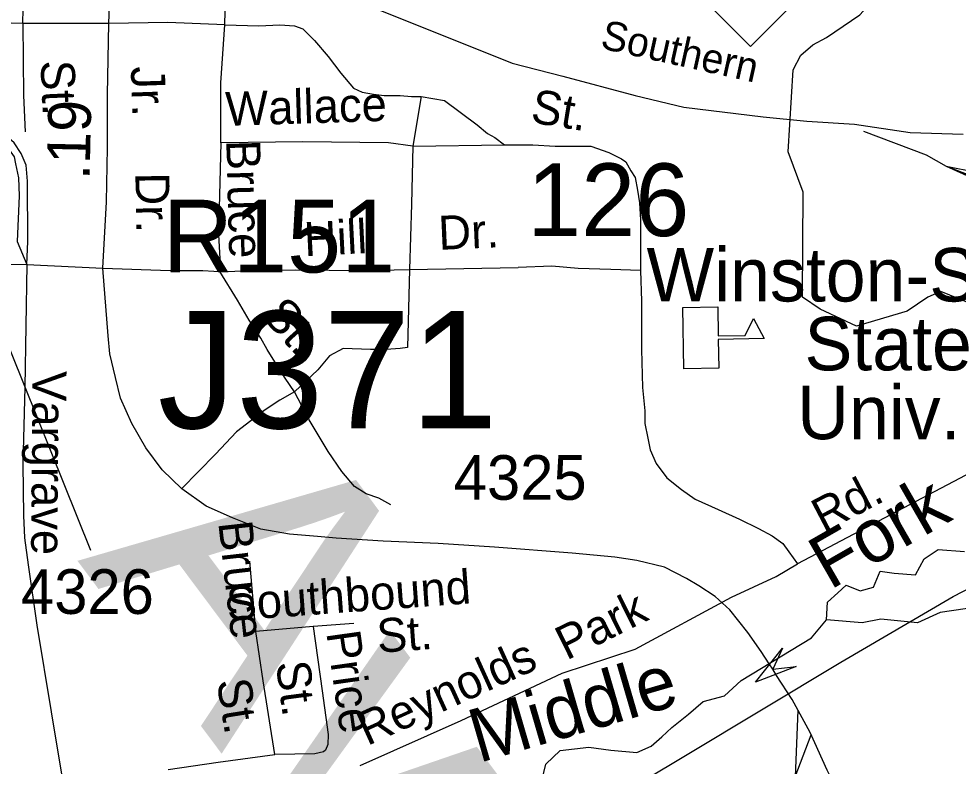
# Model space of a CAD drawing. Extents: x 1553981 to 1780076, y 812965 to 996873.
# Drawn here: x 1634089 to 1634417.6, y 847717.4 to 847978.9 of the extents above; entities that cross this region are included whole.
import ezdxf

# ---------------------------------------------------------------- set-up
doc = ezdxf.new("R2010")
doc.units = 0
for name, color, linetype in [('Exist Aviation Field Marked Auxiliary Label', 7, 'Continuous'), ('Exist Hydrographic Creek Single Shore', 7, 'Continuous'), ('Exist Hydrographic Creek Single Shore Label', 7, 'Continuous'), ('Exist Railroad Mainline', 7, 'Continuous'), ('Exist Railroad Mainline Label', 7, 'Continuous'), ('Exist Railroad Siding', 7, 'Continuous'), ('Exist Railroad Station CELL', 7, 'Continuous'), ('Exist Road Non-System Structure Non-Sys Other Number Label', 7, 'Continuous'), ('Exist Road Non-System Type 51 Label', 7, 'Continuous'), ('Exist Road Primary US Ramp 1 Lane  Attributed', 7, 'Continuous'), ('Exist Road Primary US Structure RailRoad Number Label', 7, 'Continuous'), ('Exist Road Secondary Mileage Hundredths English Label', 7, 'Continuous'), ('Exist Road Secondary Structure Standard Bridge Attributed CELL', 7, 'Continuous'), ('Exist Road Secondary Structure Standard Bridge Number Label', 7, 'Continuous'), ('Exist Road Secondary Type 51 Number Label', 7, 'Continuous'), ('Exist Road Secondary Type 51 Undivided 4 Lane Attributed', 7, 'Continuous'), ('Exist Utilities Electrical Transmission Line', 7, 'Continuous'), ('Map Preparation Border Antique Large Shape', 7, 'Continuous'), ('Map Preparation Border County Name Lower Right Label', 7, 'Continuous'), ('Map Preparation Border Division and District Label', 7, 'Continuous')]:
    doc.layers.add(name, color=color, linetype=linetype)

msp = doc.modelspace()

# ---------------------------------------------------------------- linework, layer by layer
at = {"layer": 'Exist Aviation Field Marked Auxiliary Label'}
msp.add_lwpolyline([(1634321.27, 847877.88), (1634333.51, 847878.12), (1634333.7, 847867.99), (1634343.09, 847868.17), (1634346, 847874.11), (1634349.79, 847867.1), (1634333.72, 847866.79), (1634333.92, 847856.66), (1634321.68, 847856.43)], close=True, dxfattribs=at)
at = {"layer": 'Exist Hydrographic Creek Single Shore'}
for points in [[(1634423.59, 847878.67), (1634411.61, 847883.49), (1634407.02, 847881.52), (1634399.81, 847876.6), (1634382.1, 847871.35), (1634369.34, 847877.32), (1634363.22, 847881.54), (1634363.4, 847918.28), (1634358.15, 847932.39), (1634359.93, 847961.1), (1634362.56, 847966.24), (1634366.79, 847969.8), (1634371.6, 847972.43), (1634383.27, 847980.36), (1634387.67, 847985.23), (1634390.95, 847987.86), (1634400.79, 847987.86), (1634419.72, 847994.46)], [(1634371.6, 847768.62), (1634371.93, 847774.86), (1634375.54, 847778.14), (1634378.49, 847780.76), (1634383.41, 847778.79), (1634388, 847780.11), (1634390.3, 847785.69), (1634395.22, 847785.03), (1634402.76, 847784.37), (1634405.71, 847789.95), (1634410.63, 847793.23), (1634419.81, 847792.58)], [(1634606.43, 847749.58), (1634596.26, 847749.91), (1634590.03, 847745.65), (1634551.98, 847747.94), (1634539.19, 847750.24), (1634523.45, 847757.46), (1634491.64, 847769.28), (1634473.93, 847771.25), (1634452.94, 847776.5), (1634442.11, 847775.18), (1634430.96, 847773.21), (1634420.14, 847772.56), (1634411.29, 847771.25), (1634403.41, 847767.63), (1634390.62, 847768.95), (1634384.06, 847767.63), (1634371.6, 847768.62)], [(1634263.25, 847689.52), (1634267.99, 847692.55), (1634270.9, 847700.07), (1634271.29, 847709.44), (1634273.4, 847718.14), (1634278.46, 847723), (1634288.5, 847724.08), (1634296.15, 847723.02), (1634305.25, 847722.23), (1634310.27, 847724.47), (1634313.96, 847727.77), (1634317.52, 847730.94), (1634323.32, 847735.68), (1634328.47, 847740.04), (1634335.85, 847742.04), (1634341.73, 847747.39), (1634366.35, 847762.38), (1634371.6, 847768.62)]]:
    msp.add_lwpolyline(points, dxfattribs=at)
at = {"layer": 'Exist Railroad Mainline'}
msp.add_lwpolyline([(1634084.73, 848017.96), (1634101.93, 848016.41), (1634108.26, 848015.37), (1634120.3, 848013.74), (1634133.77, 848011.8), (1634160.85, 848003.21), (1634177.74, 847996.23), (1634196.51, 847989.52), (1634235.21, 847974.07), (1634261.6, 847963.39), (1634279.34, 847958.86), (1634304.66, 847952.13), (1634321.68, 847948.04), (1634349.44, 847944.61), (1634364.74, 847943.16), (1634381.36, 847942.11), (1634400.79, 847939.11), (1634419.33, 847938.55)], dxfattribs=at)
at = {"layer": 'Exist Railroad Siding'}
for points in [[(1634384.57, 847939.61), (1634406.39, 847931.4), (1634413.4, 847927.43)], [(1634413.4, 847927.43), (1634424.06, 847925.3), (1634437.16, 847922.55), (1634465.49, 847918.59), (1634516.36, 847913.71), (1634597.31, 847909.76)], [(1634413.4, 847927.43), (1634427.73, 847921.95), (1634442.35, 847917.99), (1634462.76, 847915.85), (1634517.9, 847911.59), (1634553.23, 847908.54), (1634595.48, 847907.04)], [(1634413.4, 847927.43), (1634438.69, 847917.39), (1634466.11, 847913.43), (1634543.18, 847907.33), (1634601.57, 847901.56)], [(1634413.4, 847927.43), (1634444.47, 847913.44), (1634480.42, 847908.57), (1634539.51, 847904.3), (1634576.07, 847901.25), (1634597.94, 847900.34)]]:
    msp.add_lwpolyline(points, dxfattribs=at)
at = {"layer": 'Exist Road Primary US Ramp 1 Lane  Attributed'}
for points in [[(1634091.82, 847892.95), (1634092.26, 847900.98), (1634092.14, 847922.12), (1634091.63, 847927.72), (1634089.84, 847931.8), (1634087.43, 847935.49), (1634083.99, 847938.55), (1634081.06, 847940.59), (1634076.17, 847942.38), (1634068.98, 847942.74), (1634060.44, 847942.5), (1634050.01, 847942.24), (1634042.75, 847942.75), (1634039.7, 847943.77), (1634036.39, 847945.68), (1634022.6, 847959.97)], [(1634074.55, 847938.43), (1634076.51, 847938.43), (1634080.46, 847937.35), (1634085.49, 847933.4), (1634087.43, 847930.65), (1634087.94, 847928.23), (1634088.95, 847923.27), (1634089.21, 847917.03), (1634088.44, 847900.98), (1634091.82, 847892.95)]]:
    msp.add_lwpolyline(points, dxfattribs=at)
at = {"layer": 'Exist Road Secondary Structure Standard Bridge Attributed CELL'}
msp.add_lwpolyline([(1634360.91, 847752.39), (1634346.73, 847746.83), (1634356.23, 847758.74), (1634352.86, 847751.35)], close=True, dxfattribs=at)
at = {"layer": 'Exist Road Secondary Type 51 Number Label'}
msp.add_line((1634076.67, 847886.08), (1634114.1, 847793.03), dxfattribs=at)
at = {"layer": 'Exist Road Secondary Type 51 Undivided 4 Lane Attributed'}
for points in [[(1634118.46, 847891.68), (1634119.77, 847914.95), (1634120.06, 847933.84), (1634120.06, 847952.44), (1634120.58, 847977.25), (1634120.99, 847989.88), (1634120.3, 848013.74)], [(1634057.31, 847893.62), (1634091.82, 847892.95)], [(1634091.82, 847892.95), (1634118.46, 847891.68)], [(1634352.86, 847751.35), (1634351.54, 847753.32), (1634348.68, 847757.62), (1634344.11, 847764.2), (1634337.82, 847772.21), (1634332.67, 847776.79), (1634326.95, 847780.51), (1634322.66, 847783.09), (1634314.94, 847787.09), (1634305.21, 847789.38), (1634297.49, 847790.53), (1634282.63, 847791.94), (1634255.44, 847794.1), (1634235.73, 847795.4), (1634216.49, 847796.19), (1634200.02, 847797.2), (1634193.5, 847797.79), (1634183.78, 847798.65), (1634173.77, 847800.37), (1634163.76, 847804.38), (1634154.61, 847808.38), (1634146.08, 847814.51), (1634139.22, 847821.09), (1634133.5, 847828.82), (1634128.64, 847837.4), (1634124.64, 847846.27), (1634122.92, 847853.43), (1634120.92, 847861.72), (1634120.35, 847868.02), (1634118.46, 847891.68)], [(1634384.32, 847322.86), (1634383.63, 847348.63), (1634381.54, 847371.95), (1634380.84, 847407.81), (1634380.52, 847443.06), (1634380.93, 847454.19), (1634380.89, 847468.45), (1634381.3, 847494.71), (1634381.14, 847533.45), (1634381.94, 847573.3), (1634381.84, 847594.92), (1634382.59, 847626.93), (1634382.79, 847640.43), (1634382.28, 847656.17), (1634383.08, 847667.62), (1634382.16, 847682.68), (1634380.31, 847693.34), (1634377.76, 847702.6), (1634375.44, 847708.86), (1634371.85, 847716.12), (1634365.84, 847729.29), (1634359.55, 847740.73), (1634354.11, 847749.21), (1634352.86, 847751.35)]]:
    msp.add_lwpolyline(points, dxfattribs=at)
at = {"layer": 'Exist Utilities Electrical Transmission Line'}
msp.add_lwpolyline([(1634281.91, 847697.06), (1634321.69, 847720.79), (1634376.59, 847753.82), (1634415.85, 847776.83), (1634435.21, 847786.82)], dxfattribs=at)
at = {"layer": 'Map Preparation Border County Name Lower Right Label'}
for p, q in [((1634161.16, 847976.88), (1634161.53, 847996.4)), ((1634229.78, 847951.78), (1634226.83, 847934.43)), ((1634226.83, 847934.43), (1634258.93, 847934.8)), ((1634225.72, 847891.24), (1634224.99, 847863.93)), ((1634225.72, 847891.24), (1634263.72, 847891.98)), ((1634172.02, 847764.63), (1634169.89, 847789.16)), ((1634353.98, 847783.84), (1634361.41, 847788.24)), ((1634338.38, 847776.58), (1634353.98, 847783.84)), ((1634192.04, 847766.32), (1634172.02, 847764.63)), ((1634206.3, 847767.36), (1634192.04, 847766.32)), ((1634361.6, 847737.01), (1634360.66, 847713.74)), ((1634360.66, 847713.74), (1634366.22, 847728.45))]:
    msp.add_line(p, q, dxfattribs=at)
for points in [[(1634090.46, 847977.33), (1634090.66, 847987.7), (1634090.87, 848013.11)], [(1634090.46, 847977.33), (1634057.49, 847978.24), (1634025.74, 847978.24)], [(1634120.58, 847977.25), (1634104.67, 847977.33), (1634090.46, 847977.33)], [(1634090.46, 847977.33), (1634090.69, 847952.1), (1634091.23, 847939.36)], [(1634161.16, 847976.88), (1634141.24, 847977.62), (1634120.58, 847977.25)], [(1634159.69, 847935.54), (1634159.69, 847956.58), (1634161.16, 847976.88)], [(1634161.16, 847976.88), (1634172.97, 847976.51), (1634180.35, 847976.88), (1634185.51, 847976.51), (1634188.46, 847975.41), (1634192.52, 847971.35), (1634197.32, 847965.81), (1634201.74, 847959.9), (1634206.17, 847954.73), (1634209.12, 847953.26), (1634213.18, 847952.52), (1634216.87, 847952.15), (1634222.4, 847952.15), (1634226.46, 847951.78), (1634229.78, 847951.78)], [(1634229.78, 847951.78), (1634237.9, 847950.3), (1634249.34, 847941.81), (1634253.02, 847938.86), (1634255.61, 847937.38), (1634258.93, 847934.8)], [(1634159.69, 847935.54), (1634158.95, 847903.42), (1634159.32, 847894.93), (1634159.32, 847890.5)], [(1634226.83, 847934.43), (1634218.35, 847935.54), (1634188.46, 847935.91), (1634159.69, 847935.54)], [(1634226.83, 847934.43), (1634226.46, 847914.13), (1634225.72, 847891.24)], [(1634258.93, 847934.8), (1634268.89, 847934.8), (1634276.64, 847934.43), (1634284.01, 847934.43), (1634289.18, 847934.43), (1634295.45, 847932.22), (1634299.88, 847930), (1634301.35, 847928.89), (1634303.16, 847925.79), (1634304.67, 847923.36), (1634305.41, 847918.93), (1634306.15, 847914.5), (1634306.52, 847908.59), (1634306.52, 847900.1), (1634306.52, 847890.87)], [(1634091.82, 847892.95), (1634091.11, 847850.11), (1634090.47, 847823.11), (1634090.68, 847805.12), (1634091.07, 847797.36), (1634092.38, 847787.93), (1634095.35, 847766.78)], [(1634118.46, 847891.68), (1634141.97, 847890.83), (1634149.36, 847890.87), (1634153.42, 847890.87), (1634157.22, 847890.59), (1634159.32, 847890.5)], [(1634159.32, 847890.5), (1634185.7, 847891.17), (1634209.49, 847890.87), (1634225.72, 847891.24)], [(1634306.52, 847890.87), (1634296.19, 847891.24), (1634284.75, 847891.61), (1634275.53, 847892.35), (1634263.72, 847891.98)], [(1634185.51, 847848.42), (1634182.19, 847853.22), (1634179.24, 847858.02), (1634175.92, 847863.19), (1634173.71, 847867.25), (1634169.65, 847873.52), (1634165.59, 847880.54), (1634159.32, 847890.5)], [(1634306.52, 847890.87), (1634306.89, 847880.17), (1634306.89, 847873.15), (1634306.89, 847863.19), (1634307.26, 847849.9), (1634307.99, 847841.78), (1634307.99, 847837.35), (1634309.1, 847832.18), (1634309.84, 847828.12), (1634312.05, 847823.32), (1634315.67, 847818.3), (1634320.83, 847814.24), (1634325.63, 847810.92), (1634333.74, 847807.22), (1634341.12, 847803.9), (1634347.76, 847800.58), (1634352.56, 847798), (1634356.25, 847795.41), (1634358.46, 847792.46), (1634361.41, 847788.24)], [(1634224.99, 847863.93), (1634222.4, 847863.56), (1634217.61, 847863.19), (1634212.07, 847863.19), (1634202.48, 847863.56), (1634197.69, 847860.97), (1634193.63, 847856.17), (1634185.51, 847848.42)], [(1634185.51, 847848.42), (1634180.35, 847845.47), (1634175.18, 847842.15), (1634165.22, 847834.39), (1634157.84, 847826.64), (1634146.02, 847814.55)], [(1634219.2, 847808.89), (1634214.97, 847811.23), (1634210.52, 847812.76), (1634206.47, 847815.35), (1634202.04, 847820.51), (1634197.24, 847827.53), (1634190.6, 847838.6), (1634185.51, 847848.42)], [(1634431.16, 847824.96), (1634361.41, 847788.24)], [(1634208.42, 847717.7), (1634243.79, 847733.46), (1634279.16, 847750.04), (1634304.66, 847758.34), (1634338.38, 847776.58)], [(1634095.35, 847766.78), (1634100.39, 847736.46), (1634104.74, 847710.41)], [(1634192.04, 847766.32), (1634195.21, 847743.77), (1634197.23, 847728.49), (1634197.16, 847724.99), (1634196.39, 847723.01), (1634195.63, 847722.52), (1634192.61, 847721.81), (1634178.62, 847721.52)], [(1634178.62, 847721.52), (1634174.52, 847747.34), (1634172.02, 847764.63)], [(1634141.3, 847716.35), (1634158.83, 847718.82), (1634178.62, 847721.52)]]:
    msp.add_lwpolyline(points, dxfattribs=at)
at = {"layer": 'Map Preparation Border Division and District Label'}
msp.add_lwpolyline([(1634303.33, 848010.91), (1634344.95, 848052.54), (1634386.57, 848010.91), (1634344.95, 847969.29)], close=True, dxfattribs=at)

# ---------------------------------------------------------------- texts
at = {"layer": 'Exist Hydrographic Creek Single Shore Label'}
for s, rotation, p in [('Fork', 29.8579, (1634372.77, 847778.93)), ('Middle', 16.2769, (1634249.91, 847718.51))]:
    msp.add_text(s, height=18.75, rotation=rotation, dxfattribs=at).set_placement(p)
at = {"layer": 'Exist Railroad Mainline Label'}
msp.add_text('Southern', height=10.253, rotation=347.4598, dxfattribs=at).set_placement((1634292.1, 847968.69))
at = {"layer": 'Exist Railroad Station CELL'}
for s, p in [('Winston-Salem', (1634308.62, 847880.04)), ('State', (1634363.89, 847855.95)), ('Univ.', (1634361.34, 847831.86))]:
    msp.add_text(s, height=18.75, dxfattribs=at).set_placement(p)
at = {"layer": 'Exist Road Non-System Structure Non-Sys Other Number Label'}
msp.add_text('J371', height=41.01, dxfattribs=at).set_placement((1634137.65, 847835.68))
at = {"layer": 'Exist Road Non-System Type 51 Label'}
for s, height, rotation, p in [('St.', 11.875, 272.4344, (1634096.64, 847964.25)), ('Wallace', 11.875, 1.8134, (1634161.49, 847941.47)), ('St.', 11.875, 350.6339, (1634267.74, 847942.76)), ('Bruce', 11.875, 271.5023, (1634161.61, 847936.5)), ('Hill', 11.875, 2.9078, (1634189.09, 847895.87)), ('Dr.', 11.875, 2.5386, (1634236.04, 847898.09)), ('St.', 11.875, 311.9875, (1634173.74, 847874.83)), ('Vargrave', 11.875, 269.5345, (1634093.87, 847855.77)), ('Rd.', 11.875, 27.6243, (1634370.52, 847799.01)), ('Ave.', 95, 306.7693, (1634109.43, 847789.5)), ('Bruce', 11.875, 276.481, (1634158.8, 847802.69)), ('Southbound', 11.875, 4.1585, (1634162.1, 847768.26)), ('Park', 11.875, 26.313, (1634280.66, 847754.36)), ('St.', 11.875, 4.1585, (1634214.72, 847757.11)), ('Price', 11.875, 277.9978, (1634196.58, 847764.18)), ('Reynolds', 11.875, 24.412, (1634210.92, 847724.44)), ('St.', 11.875, 277.5191, (1634178.94, 847753.62)), ('St.', 11.875, 279.0278, (1634158.24, 847747.27))]:
    msp.add_text(s, height=height, rotation=rotation, dxfattribs=at).set_placement(p)
at = {"layer": 'Exist Road Primary US Structure RailRoad Number Label'}
msp.add_text('R151', height=25.426, dxfattribs=at).set_placement((1634139.43, 847890.2))
at = {"layer": 'Exist Road Secondary Mileage Hundredths English Label'}
msp.add_text('.19', height=15, rotation=88.7925, dxfattribs=at).set_placement((1634113.82, 847922.51))
at = {"layer": 'Exist Road Secondary Structure Standard Bridge Number Label'}
msp.add_text('126', height=25.426, dxfattribs=at).set_placement((1634266.86, 847902.92))
at = {"layer": 'Exist Road Secondary Type 51 Number Label'}
for s, p in [('4325', (1634241.19, 847810.65)), ('4326', (1634089.82, 847770.73))]:
    msp.add_text(s, height=15.625, dxfattribs=at).set_placement(p)
at = {"layer": 'Map Preparation Border Antique Large Shape'}
for s, rotation, p in [('Jr.', 271.9487, (1634128.23, 847962.18)), ('Dr.', 270.9022, (1634129.82, 847925.1))]:
    msp.add_text(s, height=11.875, rotation=rotation, dxfattribs=at).set_placement(p)

doc.saveas('drawing.dxf')
